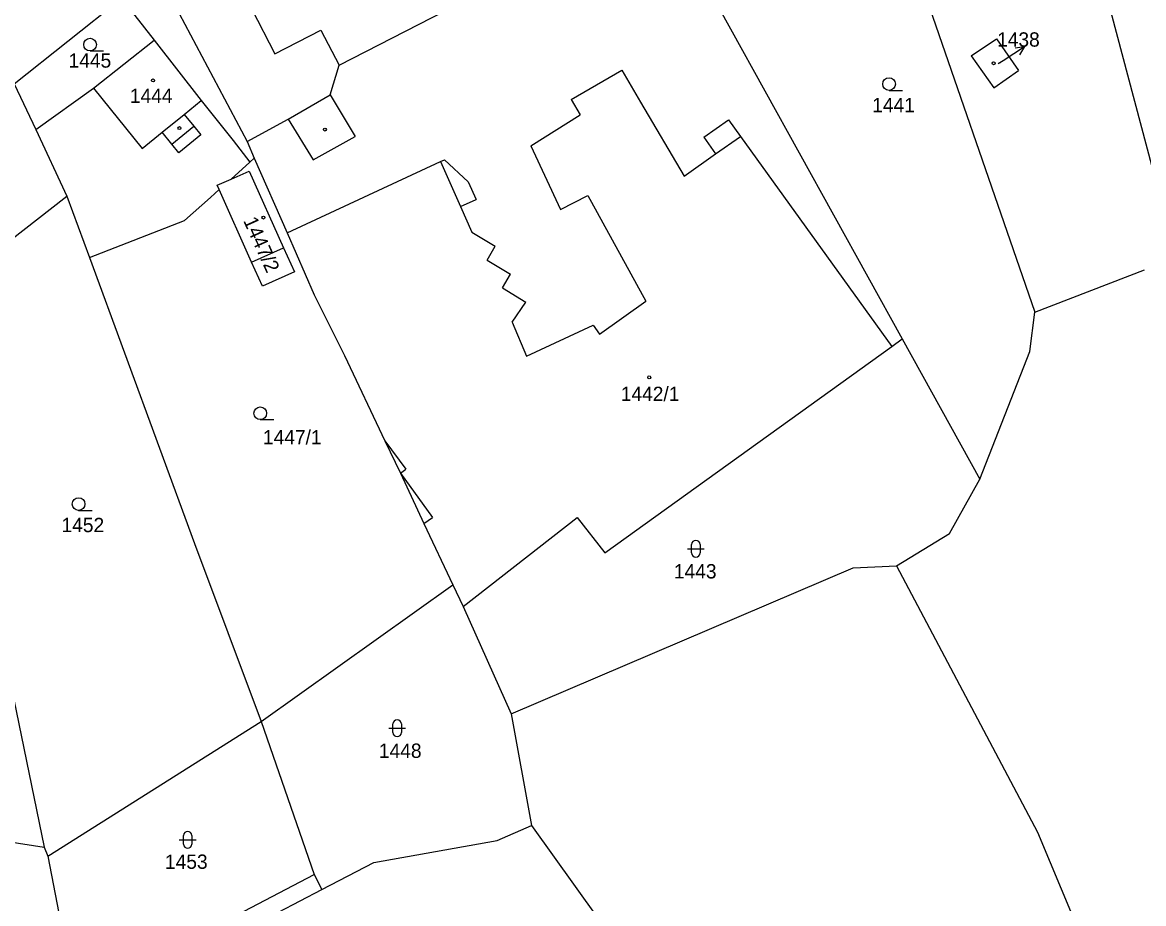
# Model space of a CAD drawing. Extents: x -785744 to -782822, y -1067550 to -1063910.
# Drawn here: x -784467.1 to -784334.2, y -1065748.7 to -1065644.2 of the extents above; entities that cross this region are included whole.
import ezdxf

# ---------------------------------------------------------------- set-up
doc = ezdxf.new("R2010")
doc.units = 0
for name, color, linetype in [('Hranice parcel', 7, 'Continuous'), ('Parcelní čísla', 7, 'Continuous'), ('Pop_ČP_popisy', 7, 'Continuous'), ('Vnitřní kresba', 7, 'Continuous'), ('Značky budov', 7, 'Continuous'), ('Značky kultur', 7, 'Continuous')]:
    doc.layers.add(name, color=color, linetype=linetype)

msp = doc.modelspace()

# ---------------------------------------------------------------- linework, layer by layer
at = {"layer": 'Hranice parcel'}
for p, q in [((-784442.38, -1065662.74), (-784440.14, -1065660.72)), ((-784444.03, -1065663.46), (-784442.38, -1065662.74)), ((-784442.38, -1065662.74), (-784440.21, -1065661.79)), ((-784440.21, -1065661.79), (-784436.14, -1065670.89)), ((-784444.81, -1065664.92), (-784443.79, -1065664)), ((-784443.79, -1065664), (-784444.03, -1065663.46)), ((-784439.94, -1065672.6), (-784443.79, -1065664)), ((-784436.14, -1065670.89), (-784434.85, -1065673.76)), ((-784438.66, -1065675.46), (-784439.94, -1065672.6)), ((-784434.85, -1065673.76), (-784438.66, -1065675.46))]:
    msp.add_line(p, q, dxfattribs=at)
for points in [[(-784343.12, -1065623.86), (-784330.22, -1065672.39)], [(-784391.3, -1065630.18), (-784362.77, -1065681.68)], [(-784362.12, -1065634.93), (-784347.05, -1065678.54)], [(-784451.2, -1065638), (-784440.48, -1065658.3)], [(-784429.57, -1065649.25), (-784410.67, -1065639.51)], [(-784468.08, -1065651.43), (-784455.35, -1065641.3)], [(-784455.35, -1065641.3), (-784451.5, -1065646.26)], [(-784439.92, -1065642.58), (-784437.17, -1065647.9)], [(-784437.17, -1065647.9), (-784431.72, -1065645.08)], [(-784431.72, -1065645.08), (-784429.57, -1065649.25)], [(-784458.67, -1065651.96), (-784451.5, -1065646.26)], [(-784451.5, -1065646.26), (-784445.91, -1065653.43)], [(-784354.61, -1065648.14), (-784351.61, -1065646.11)], [(-784351.61, -1065646.11), (-784349.01, -1065649.85)], [(-784354.61, -1065648.14), (-784351.9, -1065651.92)], [(-784430.64, -1065652.77), (-784429.57, -1065649.25)], [(-784351.9, -1065651.92), (-784349.01, -1065649.85)], [(-784468.08, -1065651.43), (-784465.53, -1065656.88)], [(-784465.53, -1065656.88), (-784458.67, -1065651.96)], [(-784445.91, -1065653.43), (-784442.11, -1065658.18)], [(-784435.6, -1065655.63), (-784430.64, -1065652.77)], [(-784440.48, -1065658.3), (-784435.6, -1065655.63)], [(-784465.53, -1065656.88), (-784461.84, -1065664.79)], [(-784442.11, -1065658.18), (-784440.14, -1065660.72)], [(-784440.48, -1065658.3), (-784439.62, -1065660.25)], [(-784440.14, -1065660.72), (-784439.62, -1065660.25)], [(-784439.62, -1065660.25), (-784435.73, -1065669.13)], [(-784476.83, -1065676.44), (-784461.84, -1065664.79)], [(-784461.84, -1065664.79), (-784459.17, -1065672.03)], [(-784447.88, -1065667.65), (-784444.81, -1065664.92)], [(-784459.17, -1065672.03), (-784447.88, -1065667.65)], [(-784435.73, -1065669.13), (-784432.52, -1065676.47)], [(-784459.17, -1065672.03), (-784446.69, -1065705.96)], [(-784347.05, -1065678.54), (-784334.06, -1065673.49)], [(-784432.52, -1065676.47), (-784428.94, -1065683.68)], [(-784347.64, -1065683.18), (-784347.05, -1065678.54)], [(-784398.06, -1065707.08), (-784364.03, -1065682.59)], [(-784364.03, -1065682.59), (-784362.77, -1065681.68)], [(-784362.77, -1065681.68), (-784353.56, -1065698.32)], [(-784428.94, -1065683.68), (-784424.15, -1065693.77)], [(-784353.56, -1065698.32), (-784347.64, -1065683.18)], [(-784424.15, -1065693.77), (-784422.29, -1065697.62)], [(-784422.29, -1065697.62), (-784419.51, -1065703.61)], [(-784357.17, -1065704.77), (-784353.56, -1065698.32)], [(-784419.51, -1065703.61), (-784416.08, -1065710.87)], [(-784414.86, -1065713.43), (-784401.34, -1065702.87)], [(-784401.34, -1065702.87), (-784398.06, -1065707.08)], [(-784363.45, -1065708.62), (-784357.17, -1065704.77)], [(-784446.69, -1065705.96), (-784438.79, -1065727.08)], [(-784409.14, -1065726.17), (-784368.59, -1065708.87)], [(-784368.59, -1065708.87), (-784363.45, -1065708.62)], [(-784363.45, -1065708.62), (-784346.73, -1065740.21)], [(-784438.79, -1065727.08), (-784416.08, -1065710.87)], [(-784416.08, -1065710.87), (-784414.86, -1065713.43)], [(-784414.86, -1065713.43), (-784409.14, -1065726.17)], [(-784469.04, -1065720.02), (-784464.54, -1065741.96)], [(-784409.14, -1065726.17), (-784406.74, -1065739.42)], [(-784464.12, -1065743.04), (-784438.79, -1065727.08)], [(-784438.79, -1065727.08), (-784432.52, -1065745.23)], [(-784483.08, -1065739.1), (-784464.54, -1065741.96)], [(-784410.8, -1065741.18), (-784406.74, -1065739.42)], [(-784406.74, -1065739.42), (-784388.72, -1065764.58)], [(-784425.46, -1065743.81), (-784410.8, -1065741.18)], [(-784346.73, -1065740.21), (-784322.38, -1065798.53)], [(-784464.54, -1065741.96), (-784464.12, -1065743.04)], [(-784464.12, -1065743.04), (-784460.81, -1065760.03)], [(-784431.59, -1065747), (-784425.46, -1065743.81)], [(-784432.52, -1065745.23), (-784431.59, -1065747)], [(-784459.88, -1065761.8), (-784431.59, -1065747)]]:
    msp.add_lwpolyline(points, dxfattribs=at)
at = {"layer": 'Pop_ČP_popisy'}
msp.add_line((-784350.81, -1065648.67), (-784348.29, -1065647.04), dxfattribs=at)
for points in [[(-784349.4, -1065647.16), (-784348.29, -1065647.04), (-784348.86, -1065648)], [(-784351.39, -1065649.05), (-784350.81, -1065648.67)]]:
    msp.add_lwpolyline(points, dxfattribs=at)
at = {"layer": 'Vnitřní kresba'}
for p, q in [((-784447.92, -1065655.07), (-784445.91, -1065653.43)), ((-784450.53, -1065657.19), (-784447.92, -1065655.07)), ((-784447.92, -1065655.07), (-784446.79, -1065656.46)), ((-784452.9, -1065659.12), (-784450.53, -1065657.19)), ((-784449.4, -1065658.59), (-784450.53, -1065657.19)), ((-784449.4, -1065658.59), (-784446.79, -1065656.46)), ((-784445.94, -1065657.49), (-784448.56, -1065659.62)), ((-784446.79, -1065656.46), (-784445.94, -1065657.49)), ((-784448.56, -1065659.62), (-784449.4, -1065658.59)), ((-784439.94, -1065672.6), (-784436.14, -1065670.89))]:
    msp.add_line(p, q, dxfattribs=at)
for points in [[(-784402.04, -1065653.32), (-784396.04, -1065649.81)], [(-784396.04, -1065649.81), (-784393.8, -1065653.63)], [(-784458.67, -1065651.96), (-784452.9, -1065659.12)], [(-784430.64, -1065652.77), (-784427.65, -1065657.69)], [(-784402.04, -1065653.32), (-784400.98, -1065655.12)], [(-784393.8, -1065653.63), (-784388.66, -1065662.39)], [(-784435.6, -1065655.63), (-784432.65, -1065660.48)], [(-784406.81, -1065658.8), (-784400.98, -1065655.12)], [(-784386.32, -1065657.79), (-784383.39, -1065655.7)], [(-784383.39, -1065655.7), (-784381.96, -1065657.68)], [(-784432.65, -1065660.48), (-784427.65, -1065657.69)], [(-784406.81, -1065658.8), (-784403.31, -1065666.36)], [(-784386.32, -1065657.79), (-784384.93, -1065659.77)], [(-784384.93, -1065659.77), (-784381.96, -1065657.68)], [(-784381.96, -1065657.68), (-784364.03, -1065682.59)], [(-784388.66, -1065662.39), (-784384.93, -1065659.77)], [(-784435.73, -1065669.13), (-784417.54, -1065660.67)], [(-784417.54, -1065660.67), (-784417.07, -1065660.45)], [(-784417.54, -1065660.67), (-784415.18, -1065665.99)], [(-784417.07, -1065660.45), (-784414.26, -1065663.06)], [(-784414.26, -1065663.06), (-784413.32, -1065665.16)], [(-784415.18, -1065665.99), (-784413.32, -1065665.16)], [(-784403.31, -1065666.36), (-784400.08, -1065664.71)], [(-784400.08, -1065664.71), (-784393.2, -1065677.21)], [(-784415.18, -1065665.99), (-784413.82, -1065669.05)], [(-784413.82, -1065669.05), (-784411.04, -1065670.71)], [(-784411.99, -1065672.38), (-784411.04, -1065670.71)], [(-784411.99, -1065672.38), (-784409.23, -1065674.01)], [(-784410.18, -1065675.64), (-784409.23, -1065674.01)], [(-784410.18, -1065675.64), (-784407.41, -1065677.35)], [(-784409.04, -1065679.73), (-784407.41, -1065677.35)], [(-784398.7, -1065681.12), (-784393.2, -1065677.21)], [(-784409.04, -1065679.73), (-784407.35, -1065683.75)], [(-784407.35, -1065683.75), (-784399.42, -1065680.06)], [(-784399.42, -1065680.06), (-784398.7, -1065681.12)], [(-784424.15, -1065693.77), (-784421.66, -1065697.16)], [(-784422.29, -1065697.62), (-784421.66, -1065697.16)], [(-784422.29, -1065697.62), (-784418.49, -1065702.87)], [(-784419.51, -1065703.61), (-784418.49, -1065702.87)], [(-784460.81, -1065760.03), (-784432.52, -1065745.23)]]:
    msp.add_lwpolyline(points, dxfattribs=at)
at = {"layer": 'Značky budov'}
for centre in [(-784351.94, -1065649.01), (-784451.63, -1065651.05), (-784448.5, -1065656.7), (-784431.25, -1065656.87), (-784438.54, -1065667.31), (-784392.78, -1065686.26)]:
    msp.add_circle(centre, 0.175, dxfattribs=at)
at = {"layer": 'Značky kultur'}
for p, q in [((-784459.1, -1065647.54), (-784457.5, -1065647.54)), ((-784364.34, -1065652.22), (-784362.74, -1065652.22)), ((-784438.91, -1065691.27), (-784437.31, -1065691.27)), ((-784460.45, -1065702.04), (-784458.85, -1065702.04)), ((-784388.26, -1065706.59), (-784386.26, -1065706.59)), ((-784387.76, -1065707.09), (-784387.76, -1065706.09)), ((-784386.76, -1065706.09), (-784386.76, -1065707.09)), ((-784423.67, -1065727.87), (-784421.67, -1065727.87)), ((-784423.17, -1065728.37), (-784423.17, -1065727.37)), ((-784422.17, -1065727.37), (-784422.17, -1065728.37)), ((-784448.52, -1065741.11), (-784446.52, -1065741.11)), ((-784448.02, -1065741.61), (-784448.02, -1065740.61)), ((-784447.02, -1065740.61), (-784447.02, -1065741.61))]:
    msp.add_line(p, q, dxfattribs=at)
for centre in [(-784459.1, -1065646.79), (-784364.34, -1065651.47), (-784438.91, -1065690.52), (-784460.45, -1065701.29)]:
    msp.add_circle(centre, 0.75, dxfattribs=at)
for centre, start, end in [((-784387.26, -1065706.09), 0, 180), ((-784387.26, -1065707.09), 180, 0), ((-784422.67, -1065727.37), 0, 180), ((-784422.67, -1065728.37), 180, 0), ((-784447.52, -1065740.61), 0, 180), ((-784447.52, -1065741.61), 180, 0)]:
    msp.add_arc(centre, 0.5, start, end, dxfattribs=at)

# ---------------------------------------------------------------- texts
at = {"layer": 'Parcelní čísla'}
for s, height, p in [('1445', 1.7, (-784461.64, -1065649.53)), ('1438', 0.1, (-784351.39, -1065649.05)), ('1444', 1.7, (-784454.37, -1065653.71)), ('1441', 1.7, (-784366.34, -1065654.81)), ('1442/1', 1.7, (-784396.16, -1065689.07)), ('1447/1', 1.7, (-784438.59, -1065694.21)), ('1452', 1.7, (-784462.48, -1065704.62)), ('1443', 1.7, (-784389.86, -1065710.11)), ('1448', 1.7, (-784424.84, -1065731.39)), ('1453', 1.7, (-784450.21, -1065744.55))]:
    msp.add_text(s, height=height, dxfattribs=at).set_placement(p)
msp.add_text('1447/2', height=1.7, rotation=294.236, dxfattribs=at).set_placement((-784440.96, -1065667.67))
at = {"layer": 'Pop_ČP_popisy'}
msp.add_text('1438', height=1.7, dxfattribs=at).set_placement((-784351.53, -1065647.04))

doc.saveas('drawing.dxf')
